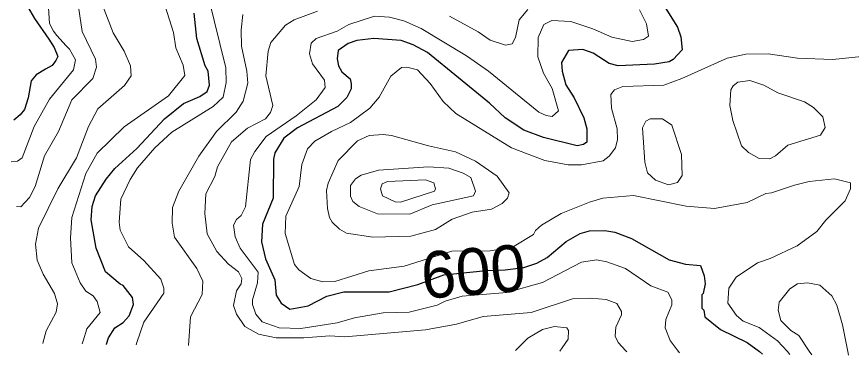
# Model space of a CAD drawing. Extents: x 673.3 to 698.5, y 6984.3 to 7012.3.
# Drawn here: x 682.735 to 684.164, y 6984.463 to 6985.044 of the extents above; entities that cross this region are included whole.
import ezdxf
from ezdxf.enums import TextEntityAlignment as Align

# ---------------------------------------------------------------- set-up
doc = ezdxf.new("R2010")
doc.units = 0
doc.header["$LTSCALE"] = 0.032
doc.layers.add('1', color=7, linetype='Continuous', lineweight=25)
doc.layers.add('2', color=7, linetype='Continuous', lineweight=13)
doc.layers.add('61', color=7, linetype='Continuous')

msp = doc.modelspace()

# ---------------------------------------------------------------- linework, layer by layer
at = {"layer": '1'}
for points in [[(682.709, 6985.1386), (682.7454, 6985.09), (682.7531, 6985.0616), (682.7652, 6985.0405), (682.7894, 6985.0055), (682.7989, 6984.9912), (682.8052, 6984.9758), (682.8017, 6984.9689), (682.7955, 6984.9604), (682.784, 6984.9541), (682.7677, 6984.9441), (682.7594, 6984.934), (682.7543, 6984.9049), (682.748, 6984.8848), (682.7405, 6984.8757), (682.7297, 6984.8665)], [(683.8297, 6985.0847), (683.8663, 6985.0259), (683.8721, 6985.0093), (683.8744, 6984.9871), (683.8587, 6984.9702), (683.8521, 6984.9664), (683.8267, 6984.9624), (683.7648, 6984.9599), (683.7492, 6984.9635), (683.7221, 6984.9811), (683.7042, 6984.9876), (683.6796, 6984.9857), (683.6677, 6984.9656), (683.6685, 6984.9507), (683.6748, 6984.9271), (683.6895, 6984.9048), (683.7057, 6984.8702), (683.7109, 6984.8519), (683.7109, 6984.829), (683.7051, 6984.8248), (683.6945, 6984.8224), (683.637, 6984.8366), (683.6031, 6984.8494)], [(682.8881, 6984.4822), (682.8882, 6984.4824), (682.8917, 6984.4934), (682.9027, 6984.5108), (682.9168, 6984.5195), (682.9269, 6984.531), (682.9346, 6984.5505), (682.9329, 6984.5625), (682.917, 6984.5832), (682.9115, 6984.5851), (682.8867, 6984.6066), (682.8708, 6984.6468), (682.8622, 6984.6954), (682.8638, 6984.7183), (682.8693, 6984.737), (682.8878, 6984.7656), (682.9028, 6984.7835), (682.94, 6984.8179), (682.9877, 6984.8689), (683.0202, 6984.8948), (683.0481, 6984.9072), (683.0606, 6984.9157), (683.0648, 6984.9263), (683.0624, 6984.9504), (683.0574, 6984.9598), (683.043, 6985.0063), (683.0382, 6985.05)], [(683.6031, 6984.8494), (683.5713, 6984.8706), (683.5445, 6984.8954), (683.4379, 6984.9827), (683.4134, 6984.9957), (683.3928, 6985.0032), (683.3462, 6985.0063), (683.3169, 6985.0032), (683.3024, 6984.9977), (683.2851, 6984.986), (683.2832, 6984.9717), (683.2855, 6984.9597), (683.2914, 6984.9492), (683.3059, 6984.9371), (683.3076, 6984.9287), (683.3073, 6984.9203), (683.2998, 6984.9051), (683.2848, 6984.8899), (683.2157, 6984.8532), (683.1919, 6984.8356), (683.1769, 6984.8105), (683.1741, 6984.7998), (683.174, 6984.7328), (683.1553, 6984.6884), (683.1537, 6984.6581), (683.1609, 6984.6288), (683.1765, 6984.5926), (683.1791, 6984.5667), (683.1873, 6984.5526), (683.2024, 6984.5424), (683.2339, 6984.5482), (683.2658, 6984.5648), (683.2947, 6984.5722), (683.3723, 6984.5724), (683.4215, 6984.5848), (683.4658, 6984.6014), (683.5385, 6984.609), (683.5711, 6984.6097), (683.6031, 6984.614), (683.6251, 6984.6214), (683.643, 6984.6313), (683.6757, 6984.6586), (683.6993, 6984.6724), (683.7156, 6984.6769), (683.742, 6984.6773), (683.7587, 6984.6747), (683.7876, 6984.6634), (683.852, 6984.6272), (683.8798, 6984.6196), (683.9055, 6984.6175), (683.9119, 6984.5999), (683.9134, 6984.5858), (683.9103, 6984.5694), (683.9079, 6984.5671), (683.9079, 6984.544), (683.9111, 6984.541), (683.9128, 6984.5292), (683.9397, 6984.5076), (683.9858, 6984.4853), (684.0065, 6984.4697), (684.0119, 6984.4656)]]:
    msp.add_lwpolyline(points, dxfattribs=at)
at = {"layer": '2'}
for points in [[(682.7301, 6985.1936), (682.7484, 6985.1491), (682.7679, 6985.1153), (682.7824, 6985.0811), (682.7887, 6985.0591), (682.7906, 6985.032), (682.7977, 6985.0193), (682.8035, 6985.0118), (682.819, 6984.994), (682.8249, 6984.9882), (682.8352, 6984.9698), (682.8317, 6984.953), (682.7909, 6984.9026), (682.7642, 6984.8559), (682.7438, 6984.8018), (682.7357, 6984.7963), (682.7253, 6984.7948)], [(682.8464, 6984.4829), (682.8482, 6984.4882), (682.8549, 6984.5086), (682.8775, 6984.5367), (682.8725, 6984.5559), (682.8652, 6984.5651), (682.8532, 6984.5733), (682.8433, 6984.5876), (682.8288, 6984.6219), (682.8264, 6984.665), (682.8288, 6984.6998), (682.8529, 6984.7748), (682.8726, 6984.8099), (682.9188, 6984.8552), (682.9943, 6984.908), (683.0225, 6984.9431), (683.0194, 6984.9605), (683.007, 6984.9906), (683.0029, 6985.0167), (682.9745, 6985.1076)], [(682.939, 6984.4815), (682.9403, 6984.4854), (682.9523, 6984.5205), (682.9867, 6984.5701), (682.9867, 6984.5783), (682.9815, 6984.5939), (682.9523, 6984.6262), (682.926, 6984.6492), (682.9117, 6984.6779), (682.9098, 6984.6914), (682.9126, 6984.7308), (682.9286, 6984.7648), (682.9413, 6984.7846), (682.9713, 6984.819), (683.0004, 6984.8457), (683.0711, 6984.8899), (683.0884, 6984.9061), (683.0934, 6984.9308), (683.0928, 6984.9561), (683.0625, 6985.0796)], [(682.7341, 6984.7183), (682.7416, 6984.7182), (682.7565, 6984.7338), (682.7663, 6984.7528), (682.7821, 6984.8055), (682.8062, 6984.8473), (682.8289, 6984.9012), (682.8647, 6984.9381), (682.8711, 6984.9575), (682.8695, 6984.9713), (682.8466, 6985.0183), (682.8386, 6985.0728)], [(682.8814, 6985.0636), (682.8995, 6985.0163)], [(683.7795, 6984.4691), (683.7778, 6984.4709), (683.7646, 6984.4851), (683.7597, 6984.4965), (683.7605, 6984.5115), (683.7702, 6984.5327), (683.7702, 6984.5387), (683.7622, 6984.5522), (683.7439, 6984.5591), (683.7179, 6984.5616), (683.6864, 6984.56), (683.6158, 6984.5369), (683.5335, 6984.5299), (683.4879, 6984.5169), (683.4345, 6984.5072), (683.2963, 6984.495), (683.2711, 6984.4966), (683.2263, 6984.4933), (683.179, 6984.4933), (683.1485, 6984.4997), (683.1255, 6984.5127), (683.1107, 6984.5337), (683.1057, 6984.5488), (683.1111, 6984.5742), (683.1189, 6984.5857), (683.1202, 6984.595), (683.1146, 6984.6064), (683.0973, 6984.6197), (683.0772, 6984.6415), (683.0609, 6984.6719), (683.0568, 6984.7067), (683.0585, 6984.74), (683.0737, 6984.7697), (683.0787, 6984.7863), (683.1024, 6984.8294), (683.1298, 6984.8527), (683.1604, 6984.8689), (683.169, 6984.8794), (683.1731, 6984.8918), (683.1611, 6984.9426), (683.1653, 6984.9845), (683.17, 6984.9996), (683.1947, 6985.0293), (683.2099, 6985.0385), (683.2498, 6985.0535)], [(683.8012, 6985.0558), (683.8129, 6985.0314), (683.8166, 6985.0107), (683.8081, 6985.0046), (683.7887, 6985.0015), (683.7538, 6985.009), (683.7211, 6985.0232), (683.6837, 6985.0355), (683.6508, 6985.0374), (683.6372, 6985.0304), (683.6276, 6985.008), (683.6269, 6984.9752), (683.6369, 6984.9472), (683.6517, 6984.9207), (683.6623, 6984.8826), (683.6518, 6984.8728), (683.6412, 6984.8743), (683.6286, 6984.8803), (683.5427, 6984.9503), (683.505, 6984.9766), (683.4271, 6985.0236), (683.3975, 6985.0366), (683.373, 6985.043), (683.3476, 6985.0446), (683.3036, 6985.0307), (683.2832, 6985.0189), (683.2472, 6985.0066), (683.2386, 6984.9982), (683.236, 6984.9801), (683.2414, 6984.963), (683.2617, 6984.9353), (683.2628, 6984.9227), (683.2473, 6984.9015), (683.2131, 6984.8741), (683.1615, 6984.8383), (683.1423, 6984.8125), (683.1352, 6984.799), (683.1262, 6984.7179), (683.119, 6984.7033), (683.1108, 6984.6963), (683.1058, 6984.6865), (683.1088, 6984.6665), (683.1175, 6984.647), (683.148, 6984.6061), (683.1472, 6984.5877), (683.1383, 6984.5587), (683.1383, 6984.5504), (683.1441, 6984.5338), (683.1549, 6984.5209), (683.1841, 6984.5105)], [(683.476, 6985.0447), (683.5246, 6985.018), (683.5454, 6985.0034), (683.5716, 6984.995), (683.5833, 6984.9972), (683.5889, 6985.0079), (683.5949, 6985.0384), (683.6101, 6985.0564)], [(683.122, 6985.0476), (683.1189, 6985.0214), (683.1197, 6984.9932), (683.1285, 6984.9504), (683.1301, 6984.9301), (683.1221, 6984.8993), (683.1104, 6984.88), (683.0767, 6984.847), (683.0464, 6984.8047), (683.0123, 6984.7449), (683.0015, 6984.7167), (683.0008, 6984.6899), (683.0045, 6984.6657), (683.0431, 6984.612), (683.0535, 6984.5907), (683.0519, 6984.5674), (683.0324, 6984.5294), (683.0285, 6984.4802)], [(682.8995, 6985.0163), (682.9186, 6984.9847), (682.9295, 6984.9597), (682.9306, 6984.9426), (682.9192, 6984.9257), (682.8736, 6984.8858), (682.8575, 6984.8555), (682.8372, 6984.8017), (682.805, 6984.7488), (682.7716, 6984.6816), (682.7669, 6984.6539), (682.7694, 6984.6266), (682.7799, 6984.6023), (682.7995, 6984.5696), (682.8044, 6984.5519), (682.8019, 6984.5374), (682.7851, 6984.5053), (682.7792, 6984.4844), (682.779, 6984.4839)], [(684.1818, 6984.9754), (684.132, 6984.9706), (684.0717, 6984.973), (684.0218, 6984.9802), (683.9831, 6984.9795), (683.9513, 6984.9727), (683.8737, 6984.9378), (683.843, 6984.9266), (683.7726, 6984.924), (683.7581, 6984.9183), (683.7523, 6984.9106), (683.7531, 6984.8868), (683.763, 6984.8517), (683.7636, 6984.8335), (683.76, 6984.819), (683.7495, 6984.8049), (683.7388, 6984.7966), (683.702, 6984.7898), (683.6792, 6984.7898), (683.6391, 6984.7974), (683.582, 6984.819), (683.4866, 6984.8778), (683.4652, 6984.8986), (683.4429, 6984.9291), (683.4208, 6984.9526), (683.4029, 6984.9574), (683.3934, 6984.9567), (683.3754, 6984.942), (683.3552, 6984.906), (683.3392, 6984.8872), (683.3063, 6984.8623), (683.2737, 6984.8472), (683.245, 6984.8304), (683.2327, 6984.8172), (683.2227, 6984.7903), (683.2181, 6984.7525), (683.1953, 6984.7018)], [(683.1953, 6984.7018), (683.1945, 6984.6722), (683.2102, 6984.619), (683.2177, 6984.6101), (683.2382, 6984.5952), (683.259, 6984.5894), (683.2794, 6984.5902), (683.3378, 6984.6081), (683.3983, 6984.6163), (683.4796, 6984.6417), (683.5456, 6984.6423), (683.5837, 6984.649), (683.6198, 6984.6707), (683.6228, 6984.6771), (683.6336, 6984.6865), (683.6668, 6984.7066), (683.7156, 6984.7262), (683.7384, 6984.7327), (683.7909, 6984.7375), (683.8812, 6984.7189), (683.9299, 6984.7148), (683.9857, 6984.7255), (684.0173, 6984.7408), (684.027, 6984.7417), (684.0666, 6984.7553), (684.0919, 6984.7612), (684.1352, 6984.7661), (684.1627, 6984.7592), (684.1627, 6984.749), (684.1532, 6984.7283), (684.1203, 6984.6952), (684.1048, 6984.6758), (684.071, 6984.651), (684.0249, 6984.6291), (684.0033, 6984.622), (683.9665, 6984.5972), (683.9543, 6984.5787), (683.9527, 6984.5528), (683.9672, 6984.5316), (683.979, 6984.5217), (684.0062, 6984.5113), (684.0377, 6984.488), (684.0545, 6984.4697), (684.0589, 6984.4649)], [(683.1841, 6984.5105), (683.2212, 6984.5094), (683.2836, 6984.519), (683.3131, 6984.5274), (683.362, 6984.5364), (683.4067, 6984.5373), (683.4544, 6984.5493), (683.4681, 6984.5563), (683.4975, 6984.5649), (683.5741, 6984.5712), (683.6348, 6984.588), (683.7017, 6984.6232), (683.7276, 6984.6268), (683.7453, 6984.6235), (683.777, 6984.6124), (683.8205, 6984.5825), (683.8495, 6984.5719), (683.8565, 6984.5584), (683.8565, 6984.5498), (683.8465, 6984.525), (683.8452, 6984.5108), (683.8536, 6984.4886), (683.8656, 6984.473), (683.8696, 6984.4678)], [(684.0961, 6984.4644), (684.092, 6984.4705), (684.0739, 6984.4973), (684.0601, 6984.5061), (684.0434, 6984.5232), (684.0389, 6984.5406), (684.0406, 6984.5543), (684.0588, 6984.5773), (684.0716, 6984.5861), (684.0892, 6984.5877), (684.1099, 6984.5834), (684.1308, 6984.5656), (684.139, 6984.5495), (684.149, 6984.5158), (684.1579, 6984.4697), (684.1591, 6984.4634)], [(683.5886, 6984.4719), (683.6014, 6984.4845), (683.61, 6984.493), (683.6353, 6984.5077), (683.6554, 6984.5128), (683.6765, 6984.5103), (683.6798, 6984.506), (683.6789, 6984.4909), (683.6685, 6984.4763), (683.6646, 6984.4708)]]:
    msp.add_lwpolyline(points, dxfattribs=at)
for points in [[(684.0835, 6984.8981), (684.0381, 6984.9136), (684.014, 6984.9264), (683.9902, 6984.9345), (683.9694, 6984.9319), (683.9615, 6984.9255), (683.9577, 6984.9187), (683.9559, 6984.8917), (683.9609, 6984.8657), (683.9761, 6984.8226), (683.9876, 6984.811), (684.0063, 6984.8007), (684.0242, 6984.8002), (684.0343, 6984.8056), (684.0552, 6984.8239), (684.1112, 6984.841), (684.1194, 6984.8541), (684.1149, 6984.8723), (684.0993, 6984.8883)], [(683.8061, 6984.8532), (683.812, 6984.8648), (683.8195, 6984.8689), (683.8405, 6984.8688), (683.8564, 6984.8581), (683.8729, 6984.8074), (683.8744, 6984.7719), (683.8663, 6984.7597), (683.8511, 6984.7556), (683.8284, 6984.7639), (683.8151, 6984.7762), (683.8102, 6984.7944)], [(683.5144, 6984.709), (683.5477, 6984.7139), (683.5657, 6984.7236), (683.5753, 6984.7325), (683.5779, 6984.7417), (683.5574, 6984.7704), (683.5205, 6984.7961), (683.486, 6984.8122), (683.44, 6984.8223), (683.3764, 6984.8403), (683.3621, 6984.8419), (683.3381, 6984.8403), (683.3184, 6984.8312), (683.285, 6984.7972), (683.2677, 6984.7586), (683.2653, 6984.746), (683.2669, 6984.7151), (683.2702, 6984.6995), (683.2746, 6984.6916), (683.2872, 6984.6797), (683.2995, 6984.6728), (683.3446, 6984.6659), (683.4094, 6984.6676), (683.4516, 6984.6789), (683.4806, 6984.6966)], [(683.5169, 6984.7369), (683.5201, 6984.7447), (683.5124, 6984.768), (683.4993, 6984.7757), (683.4749, 6984.784), (683.4398, 6984.7864), (683.3544, 6984.7808), (683.3242, 6984.7723), (683.3146, 6984.7658), (683.3061, 6984.7543), (683.3061, 6984.7364), (683.3101, 6984.7272), (683.3213, 6984.7185), (683.3525, 6984.7059), (683.408, 6984.7051), (683.4462, 6984.7216)], [(683.4499, 6984.7449), (683.4517, 6984.7489), (683.4489, 6984.7591), (683.4344, 6984.7644), (683.3698, 6984.7612), (683.3605, 6984.7572), (683.3574, 6984.7487), (683.3613, 6984.737), (683.3829, 6984.7263), (683.3917, 6984.726)]]:
    msp.add_lwpolyline(points, close=True, dxfattribs=at)

# ---------------------------------------------------------------- texts
at = {"layer": '61'}
msp.add_text('600', height=0.08, rotation=4.693, dxfattribs=at).set_placement((683.5195, 6984.5673), align=Align.CENTER)

doc.saveas('drawing.dxf')
